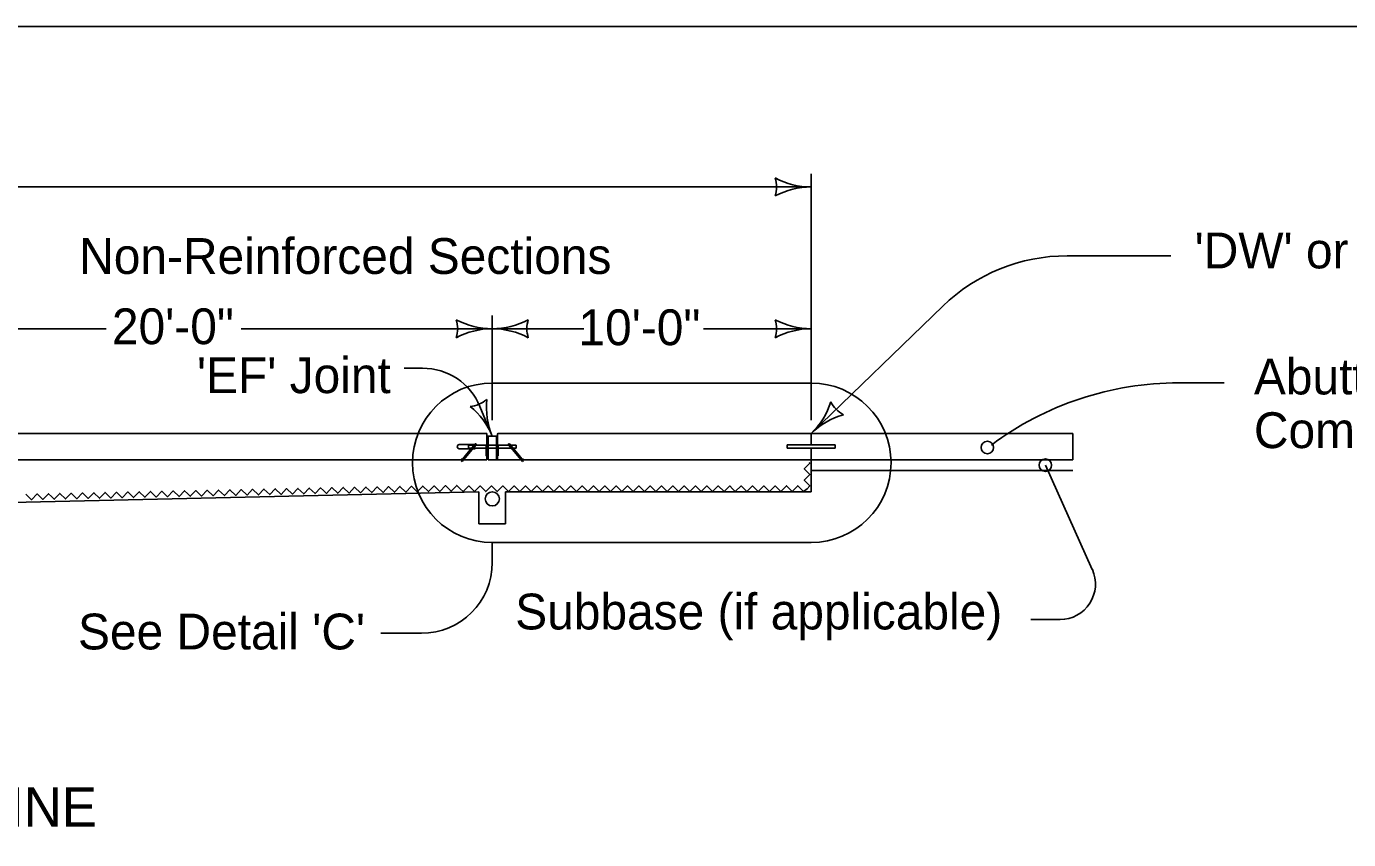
# Model space of a CAD drawing. Extents: x -2135039 to -2120895, y -2139150 to -2136566.
# Drawn here: x -2126431 to -2125693, y -2137490 to -2137036 of the extents above; entities that cross this region are included whole.
import ezdxf

# ---------------------------------------------------------------- set-up
doc = ezdxf.new("R2010")
doc.units = 0
for name, color, linetype in [('dsnStdDimension', 7, 'Continuous'), ('dsnStdLabel', 7, 'Continuous'), ('dsnStdLineWork', 7, 'Continuous'), ('Level 1', 7, 'Continuous'), ('Level 2', 7, 'Continuous'), ('Level 3', 7, 'Continuous')]:
    doc.layers.add(name, color=color, linetype=linetype)

msp = doc.modelspace()

# ---------------------------------------------------------------- linework, layer by layer
at = {"layer": 'dsnStdDimension'}
for p, q in [((-2125992.85, -2137255.84), (-2125992.85, -2137118.21)), ((-2127329.35, -2137125.64), (-2125992.85, -2137125.64)), ((-2126171.05, -2137255.84), (-2126171.05, -2137197.41)), ((-2126527.45, -2137204.84), (-2126386.67, -2137204.84)), ((-2126311.39, -2137204.84), (-2126171.05, -2137204.84)), ((-2126171.05, -2137204.84), (-2126119.93, -2137204.84)), ((-2126052.97, -2137204.84), (-2125992.85, -2137204.84))]:
    msp.add_line(p, q, dxfattribs=at)
for centre, radius, start, end in [((-2126028.7, -2137125.64), 16.51, 342.26665, 17.73335), ((-2125992.85, -2137082.89), 42.75, 241.92751, 270), ((-2126028.7, -2137125.64), 16.51, 342.26665, 17.73335), ((-2125992.85, -2137082.89), 42.75, 241.92751, 270), ((-2125992.85, -2137168.39), 42.75, 90, 118.07249), ((-2125992.85, -2137168.39), 42.75, 90, 118.07249), ((-2126206.9, -2137204.84), 16.51, 342.26665, 17.73335), ((-2126171.05, -2137162.09), 42.75, 241.92751, 270), ((-2126206.9, -2137204.84), 16.51, 342.26665, 17.73335), ((-2126171.05, -2137162.09), 42.75, 241.92751, 270), ((-2126171.05, -2137162.09), 42.75, 270, 298.07249), ((-2126171.05, -2137162.09), 42.75, 270, 298.07249), ((-2126135.21, -2137204.84), 16.51, 162.26665, 197.73335), ((-2126135.21, -2137204.84), 16.51, 162.26665, 197.73335), ((-2126028.7, -2137204.84), 16.51, 342.26665, 17.73335), ((-2125992.85, -2137162.09), 42.75, 241.92751, 270), ((-2126028.7, -2137204.84), 16.51, 342.26665, 17.73335), ((-2125992.85, -2137162.09), 42.75, 241.92751, 270), ((-2126171.05, -2137247.58), 42.75, 90, 118.07249), ((-2126171.05, -2137247.58), 42.75, 90, 118.07249), ((-2126171.05, -2137247.58), 42.75, 61.92751, 90), ((-2126171.05, -2137247.58), 42.75, 61.92751, 90), ((-2125992.85, -2137247.58), 42.75, 90, 118.07249), ((-2125992.85, -2137247.58), 42.75, 90, 118.07249)]:
    msp.add_arc(centre, radius, start, end, dxfattribs=at)
at = {"layer": 'dsnStdLabel'}
for p, q in [((-2125849.87, -2137164.08), (-2125791.98, -2137164.08)), ((-2125992.85, -2137263.26), (-2125919.4, -2137192.21)), ((-2126220.32, -2137226.87), (-2126209.98, -2137226.87)), ((-2126171.05, -2137235.17), (-2125992.85, -2137235.17)), ((-2125787.52, -2137235.01), (-2125762.18, -2137235.01)), ((-2126177.99, -2137248.21), (-2126171.05, -2137264.87)), ((-2125835.83, -2137339.33), (-2125862.07, -2137281.03)), ((-2126171.05, -2137324.27), (-2126171.05, -2137335.37)), ((-2126171.05, -2137324.27), (-2125992.85, -2137324.27)), ((-2125870.11, -2137367.25), (-2125853.87, -2137367.25)), ((-2126233.3, -2137374.97), (-2126210.65, -2137374.97))]:
    msp.add_line(p, q, dxfattribs=at)
for centre in [(-2125894.47, -2137271.16), (-2125862.07, -2137281.03)]:
    msp.add_circle(centre, 3.46, dxfattribs=at)
for centre, radius, start, end in [((-2125849.87, -2137264.08), 100, 90, 134.0496), ((-2126209.98, -2137261.52), 34.65, 22.59071, 90), ((-2126171.05, -2137279.72), 44.55, 90, 270), ((-2125992.85, -2137279.72), 44.55, 270, 90), ((-2125787.52, -2137410.01), 175, 90, 126.74873), ((-2126184.82, -2137231.78), 16.51, 274.85846, 310.32516), ((-2126131.59, -2137248.45), 42.75, 174.51932, 202.59181), ((-2126210.52, -2137281.29), 42.75, 22.59181, 50.6643), ((-2126022.58, -2137232.54), 42.75, 314.04979, 342.12228), ((-2126022.58, -2137232.54), 42.75, 314.04979, 342.12228), ((-2125967.09, -2137238.34), 16.51, 206.31644, 241.78314), ((-2125967.09, -2137238.34), 16.51, 206.31644, 241.78314), ((-2125963.13, -2137293.99), 42.75, 105.97731, 134.04979), ((-2125963.13, -2137293.99), 42.75, 105.97731, 134.04979), ((-2126210.65, -2137335.37), 39.6, 270, 360), ((-2125853.87, -2137347.45), 19.8, 270, 24.23803)]:
    msp.add_arc(centre, radius, start, end, dxfattribs=at)
at = {"layer": 'dsnStdLineWork'}
for p, q in [((-2126174.02, -2137264.87), (-2126173.43, -2137264.87)), ((-2126168.68, -2137264.87), (-2126168.08, -2137264.87)), ((-2125996.2, -2137278.11), (-2125998.11, -2137278.11))]:
    msp.add_line(p, q, dxfattribs=at)
for points in [[(-2125995.17, -2137294.22), (-2125993.58, -2137292.64), (-2125996.75, -2137289.47), (-2125993.59, -2137286.3), (-2125996.76, -2137283.14), (-2125993.59, -2137279.97), (-2125994.02, -2137279.53)], [(-2126431.66, -2137297.24), (-2126428.42, -2137300.34), (-2126425.33, -2137297.1), (-2126422.09, -2137300.2), (-2126418.99, -2137296.97), (-2126417.37, -2137298.52)], [(-2126417.37, -2137298.52), (-2126415.75, -2137300.07), (-2126412.65, -2137296.83), (-2126409.42, -2137299.93), (-2126406.32, -2137296.69), (-2126403.09, -2137299.8), (-2126399.99, -2137296.56), (-2126396.75, -2137299.66), (-2126393.65, -2137296.43), (-2126390.41, -2137299.53), (-2126387.32, -2137296.29), (-2126384.08, -2137299.39), (-2126380.98, -2137296.16), (-2126377.75, -2137299.25), (-2126374.64, -2137296.02), (-2126371.41, -2137299.12), (-2126368.31, -2137295.88), (-2126365.08, -2137298.98), (-2126361.98, -2137295.75), (-2126358.74, -2137298.85), (-2126355.65, -2137295.61), (-2126352.41, -2137298.71), (-2126349.31, -2137295.47), (-2126346.07, -2137298.58), (-2126342.97, -2137295.34), (-2126341.36, -2137296.89)], [(-2126341.36, -2137296.89), (-2126339.74, -2137298.44), (-2126336.64, -2137295.21), (-2126333.41, -2137298.31), (-2126330.3, -2137295.07), (-2126327.07, -2137298.17), (-2126323.97, -2137294.94), (-2126320.73, -2137298.03), (-2126317.64, -2137294.8), (-2126314.4, -2137297.9), (-2126311.3, -2137294.66), (-2126308.07, -2137297.76), (-2126304.97, -2137294.53), (-2126301.73, -2137297.63), (-2126298.63, -2137294.39), (-2126295.4, -2137297.49), (-2126292.3, -2137294.26), (-2126289.06, -2137297.36), (-2126285.96, -2137294.12), (-2126282.73, -2137297.22), (-2126279.63, -2137293.99), (-2126276.39, -2137297.09), (-2126273.29, -2137293.85), (-2126270.06, -2137296.95), (-2126266.96, -2137293.72), (-2126265.34, -2137295.27)], [(-2126265.34, -2137295.27), (-2126263.73, -2137296.82), (-2126260.62, -2137293.6), (-2126257.39, -2137296.71), (-2126254.28, -2137293.49), (-2126251.06, -2137296.6), (-2126247.95, -2137293.38), (-2126244.72, -2137296.49), (-2126241.61, -2137293.27), (-2126238.39, -2137296.38), (-2126235.28, -2137293.16), (-2126232.05, -2137296.27), (-2126228.94, -2137293.05), (-2126225.72, -2137296.16), (-2126222.61, -2137292.94), (-2126219.38, -2137296.05), (-2126216.27, -2137292.83), (-2126213.05, -2137295.94), (-2126209.94, -2137292.72), (-2126206.71, -2137295.83), (-2126203.6, -2137292.61), (-2126200.38, -2137295.72), (-2126197.27, -2137292.49), (-2126194.04, -2137295.61), (-2126190.93, -2137292.38), (-2126188.99, -2137294.26)], [(-2126188.91, -2137294.24), (-2126187.33, -2137295.82), (-2126184.16, -2137292.66), (-2126180.99, -2137295.82), (-2126177.83, -2137292.66), (-2126174.66, -2137295.82), (-2126171.49, -2137292.65), (-2126168.32, -2137295.82), (-2126165.15, -2137292.65), (-2126161.99, -2137295.82), (-2126158.82, -2137292.65), (-2126155.65, -2137295.82), (-2126152.48, -2137292.64), (-2126149.31, -2137295.81), (-2126146.15, -2137292.64), (-2126142.98, -2137295.81), (-2126139.81, -2137292.64), (-2126136.64, -2137295.81), (-2126133.47, -2137292.64), (-2126130.31, -2137295.8), (-2126127.14, -2137292.63), (-2126123.97, -2137295.8), (-2126120.8, -2137292.63), (-2126117.63, -2137295.8), (-2126114.47, -2137292.63), (-2126112.88, -2137294.21)], [(-2126112.88, -2137294.21), (-2126111.3, -2137295.8), (-2126108.13, -2137292.62), (-2126104.96, -2137295.79), (-2126101.79, -2137292.62), (-2126098.63, -2137295.79), (-2126095.46, -2137292.62), (-2126092.29, -2137295.79), (-2126089.12, -2137292.62), (-2126085.95, -2137295.78), (-2126082.79, -2137292.62), (-2126079.62, -2137295.78), (-2126076.45, -2137292.62), (-2126073.28, -2137295.78), (-2126070.11, -2137292.61), (-2126066.95, -2137295.78), (-2126063.78, -2137292.61), (-2126060.61, -2137295.78), (-2126057.44, -2137292.61), (-2126054.27, -2137295.78), (-2126051.11, -2137292.6), (-2126047.94, -2137295.77), (-2126044.77, -2137292.6), (-2126041.6, -2137295.77), (-2126038.43, -2137292.6), (-2126036.85, -2137294.18)], [(-2126036.85, -2137294.18), (-2126035.27, -2137295.77), (-2126032.1, -2137292.6), (-2126028.93, -2137295.76), (-2126025.76, -2137292.59), (-2126022.59, -2137295.76), (-2126019.43, -2137292.59), (-2126016.26, -2137295.76), (-2126013.09, -2137292.59), (-2126009.92, -2137295.76), (-2126006.75, -2137292.58), (-2126003.59, -2137295.75), (-2126000.42, -2137292.58), (-2125997.25, -2137295.75), (-2125995.17, -2137294.22)]]:
    msp.add_lwpolyline(points, dxfattribs=at)
at = {"layer": 'Level 1'}
msp.add_lwpolyline([(-2127734.46, -2137035.95), (-2124599.46, -2137035.95), (-2124599.46, -2139045.94), (-2127734.46, -2139045.94)], close=True, dxfattribs=at)
at = {"layer": 'Level 2'}
for p, q in [((-2127329.35, -2137263.26), (-2126174.44, -2137263.26)), ((-2126174.44, -2137263.26), (-2126527.46, -2137263.26)), ((-2126174.03, -2137269.78), (-2126174.03, -2137263.68)), ((-2126174.02, -2137273.6), (-2126174.02, -2137263.68)), ((-2126173.97, -2137264.87), (-2126173.97, -2137273.6)), ((-2126173.91, -2137264.87), (-2126173.91, -2137273.6)), ((-2126173.85, -2137264.87), (-2126173.85, -2137273.6)), ((-2126173.79, -2137264.87), (-2126173.79, -2137273.6)), ((-2126173.73, -2137264.87), (-2126173.73, -2137273.6)), ((-2126173.67, -2137264.87), (-2126173.67, -2137273.6)), ((-2126173.61, -2137264.87), (-2126173.61, -2137273.6)), ((-2126173.55, -2137264.87), (-2126173.55, -2137273.6)), ((-2126173.49, -2137264.87), (-2126173.49, -2137273.6)), ((-2126173.43, -2137264.87), (-2126173.43, -2137269.8)), ((-2126168.68, -2137264.87), (-2126173.43, -2137264.87)), ((-2126173.43, -2137264.87), (-2126173.43, -2137269.8)), ((-2126168.68, -2137269.8), (-2126168.68, -2137264.87)), ((-2126168.62, -2137264.87), (-2126168.62, -2137273.6)), ((-2126168.56, -2137264.87), (-2126168.56, -2137273.6)), ((-2126168.5, -2137264.87), (-2126168.5, -2137273.6)), ((-2126168.44, -2137264.87), (-2126168.44, -2137273.6)), ((-2126168.39, -2137264.87), (-2126168.39, -2137273.6)), ((-2126168.32, -2137264.87), (-2126168.32, -2137273.6)), ((-2126168.27, -2137264.87), (-2126168.27, -2137273.6)), ((-2126168.2, -2137264.87), (-2126168.2, -2137273.6)), ((-2126168.15, -2137264.87), (-2126168.15, -2137273.6)), ((-2126168.09, -2137263.68), (-2126168.09, -2137269.8)), ((-2126168.08, -2137273.6), (-2126168.08, -2137263.68)), ((-2126167.67, -2137263.26), (-2125992.85, -2137263.26)), ((-2125992.86, -2137263.27), (-2126167.67, -2137263.26)), ((-2125992.86, -2137269.76), (-2125992.86, -2137263.27)), ((-2125992.85, -2137263.26), (-2125992.85, -2137269.76)), ((-2125992.85, -2137263.26), (-2125846.67, -2137263.26)), ((-2125846.67, -2137263.26), (-2125846.67, -2137278.11)), ((-2126189.47, -2137269.5), (-2126180.91, -2137269.5)), ((-2126189.47, -2137271.88), (-2126182.9, -2137271.88)), ((-2126184.34, -2137273.6), (-2126186.09, -2137275.69)), ((-2126183.41, -2137273.6), (-2126185.17, -2137275.69)), ((-2126184.42, -2137271.58), (-2126184.42, -2137269.8)), ((-2126184.42, -2137269.8), (-2126181.15, -2137269.8)), ((-2126184.42, -2137271.58), (-2126182.65, -2137271.58)), ((-2126180.66, -2137269.21), (-2126184.34, -2137273.6)), ((-2126183.41, -2137273.6), (-2126180.12, -2137269.67)), ((-2126181.97, -2137271.88), (-2126180.56, -2137271.88)), ((-2126181.72, -2137271.58), (-2126174.38, -2137271.58)), ((-2126180.56, -2137271.58), (-2126180.56, -2137271.88)), ((-2126180.23, -2137269.8), (-2126174.38, -2137269.8)), ((-2126174.39, -2137275.74), (-2126174.39, -2137269.8)), ((-2126174.38, -2137275.74), (-2126174.38, -2137269.8)), ((-2126174.02, -2137275.69), (-2126174.02, -2137273.6)), ((-2126173.97, -2137273.6), (-2126173.97, -2137275.69)), ((-2126173.91, -2137273.6), (-2126173.91, -2137275.69)), ((-2126173.85, -2137273.6), (-2126173.85, -2137275.69)), ((-2126173.79, -2137273.6), (-2126173.79, -2137275.69)), ((-2126173.73, -2137273.6), (-2126173.73, -2137275.69)), ((-2126173.67, -2137273.6), (-2126173.67, -2137275.69)), ((-2126173.61, -2137273.6), (-2126173.61, -2137275.69)), ((-2126173.55, -2137273.6), (-2126173.55, -2137275.69)), ((-2126173.49, -2137273.6), (-2126173.49, -2137275.69)), ((-2126173.43, -2137269.8), (-2126173.43, -2137271.58)), ((-2126173.43, -2137269.8), (-2126168.68, -2137269.8)), ((-2126173.43, -2137271.58), (-2126168.68, -2137271.58)), ((-2126173.43, -2137271.58), (-2126173.43, -2137273.6)), ((-2126173.43, -2137273.6), (-2126173.43, -2137275.69)), ((-2126168.68, -2137269.8), (-2126168.68, -2137271.58)), ((-2126168.68, -2137271.58), (-2126168.68, -2137273.6)), ((-2126168.68, -2137273.6), (-2126168.68, -2137275.69)), ((-2126168.62, -2137273.6), (-2126168.62, -2137275.69)), ((-2126168.56, -2137273.6), (-2126168.56, -2137275.69)), ((-2126168.5, -2137273.6), (-2126168.5, -2137275.69)), ((-2126168.44, -2137273.6), (-2126168.44, -2137275.69)), ((-2126168.39, -2137273.6), (-2126168.39, -2137275.69)), ((-2126168.32, -2137273.6), (-2126168.32, -2137275.69)), ((-2126168.27, -2137273.6), (-2126168.27, -2137275.69)), ((-2126168.2, -2137273.6), (-2126168.2, -2137275.69)), ((-2126168.15, -2137273.6), (-2126168.15, -2137275.69)), ((-2126168.08, -2137275.69), (-2126168.08, -2137273.6)), ((-2126167.73, -2137269.8), (-2126167.73, -2137275.74)), ((-2126167.73, -2137275.74), (-2126167.73, -2137269.8)), ((-2126167.73, -2137269.8), (-2126161.89, -2137269.8)), ((-2126167.73, -2137271.58), (-2126160.39, -2137271.58)), ((-2126158.7, -2137273.6), (-2126161.99, -2137269.67)), ((-2126161.45, -2137269.21), (-2126157.77, -2137273.6)), ((-2126160.96, -2137269.8), (-2126157.69, -2137269.8)), ((-2126159.46, -2137271.58), (-2126157.69, -2137271.58)), ((-2126158.7, -2137273.6), (-2126156.94, -2137275.69)), ((-2126157.77, -2137273.6), (-2126156.01, -2137275.69)), ((-2126157.69, -2137271.58), (-2126157.69, -2137269.8)), ((-2126006.23, -2137271.62), (-2126006.23, -2137269.76)), ((-2126006.23, -2137269.76), (-2125992.86, -2137269.76)), ((-2125992.86, -2137271.62), (-2126006.23, -2137271.62)), ((-2126006.22, -2137271.62), (-2126006.22, -2137269.76)), ((-2126006.22, -2137269.76), (-2125979.49, -2137269.76)), ((-2125979.49, -2137271.62), (-2126006.22, -2137271.62)), ((-2125992.86, -2137278.11), (-2125992.86, -2137271.62)), ((-2125992.85, -2137271.62), (-2125992.85, -2137278.11)), ((-2125979.49, -2137269.76), (-2125979.49, -2137271.62)), ((-2126188.13, -2137278.11), (-2127329.35, -2137278.11)), ((-2126527.46, -2137278.11), (-2126188.14, -2137278.11)), ((-2126186.09, -2137275.69), (-2126188.51, -2137278.57)), ((-2126187.96, -2137279.03), (-2126188.51, -2137278.57)), ((-2126188.14, -2137278.11), (-2126174.03, -2137278.11)), ((-2126185.17, -2137275.69), (-2126187.96, -2137279.03)), ((-2126174.02, -2137278.11), (-2126187.2, -2137278.11)), ((-2126174.03, -2137278.11), (-2126174.03, -2137275.74)), ((-2126174.02, -2137278.11), (-2126174.02, -2137275.69)), ((-2126173.97, -2137275.69), (-2126173.97, -2137278.11)), ((-2126173.91, -2137275.69), (-2126173.91, -2137278.11)), ((-2126173.85, -2137275.69), (-2126173.85, -2137278.11)), ((-2126173.79, -2137275.69), (-2126173.79, -2137278.11)), ((-2126173.73, -2137275.69), (-2126173.73, -2137278.11)), ((-2126173.67, -2137275.69), (-2126173.67, -2137278.11)), ((-2126173.61, -2137275.69), (-2126173.61, -2137278.11)), ((-2126173.55, -2137275.69), (-2126173.55, -2137278.11)), ((-2126173.49, -2137275.69), (-2126173.49, -2137278.11)), ((-2126173.43, -2137275.69), (-2126173.43, -2137278.11)), ((-2126173.43, -2137278.11), (-2126168.68, -2137278.11)), ((-2126168.68, -2137275.69), (-2126168.68, -2137278.11)), ((-2126168.68, -2137278.11), (-2125992.85, -2137278.11)), ((-2126168.62, -2137275.69), (-2126168.62, -2137278.11)), ((-2126168.56, -2137275.69), (-2126168.56, -2137278.11)), ((-2126168.5, -2137275.69), (-2126168.5, -2137278.11)), ((-2126168.44, -2137275.69), (-2126168.44, -2137278.11)), ((-2126168.39, -2137275.69), (-2126168.39, -2137278.11)), ((-2126168.32, -2137275.69), (-2126168.32, -2137278.11)), ((-2126168.27, -2137275.69), (-2126168.27, -2137278.11)), ((-2126168.2, -2137275.69), (-2126168.2, -2137278.11)), ((-2126168.15, -2137275.69), (-2126168.15, -2137278.11)), ((-2126168.09, -2137275.74), (-2126168.09, -2137278.11)), ((-2126168.09, -2137278.11), (-2125992.86, -2137278.11)), ((-2126168.08, -2137278.11), (-2126168.08, -2137275.69)), ((-2126156.94, -2137275.69), (-2126154.15, -2137279.03)), ((-2126156.01, -2137275.69), (-2126153.6, -2137278.57)), ((-2126154.15, -2137279.03), (-2126153.6, -2137278.57)), ((-2125992.85, -2137278.11), (-2125992.85, -2137295.93)), ((-2125992.85, -2137278.11), (-2125846.67, -2137278.11)), ((-2125846.67, -2137284.05), (-2125992.85, -2137284.05)), ((-2126178.48, -2137295.93), (-2127295.72, -2137321.18)), ((-2126178.48, -2137295.93), (-2126178.48, -2137313.75)), ((-2126163.63, -2137295.93), (-2125992.85, -2137295.93)), ((-2126163.63, -2137295.93), (-2126163.63, -2137313.75)), ((-2126178.48, -2137313.75), (-2126163.63, -2137313.75))]:
    msp.add_line(p, q, dxfattribs=at)
msp.add_lwpolyline([(-2126168.09, -2137269.8), (-2126168.09, -2137269.8)], dxfattribs=at)
for centre, radius in [((-2126183.41, -2137272.12), 0.238), ((-2126158.95, -2137271.82), 0.238), ((-2126188.24, -2137277.88), 0.238), ((-2126153.87, -2137277.88), 0.238), ((-2126171.05, -2137299.89), 3.96)]:
    msp.add_circle(centre, radius, dxfattribs=at)
for centre, radius, start, end in [((-2126174.44, -2137263.68), 0.416, 360, 90), ((-2126174.44, -2137263.68), 0.416, 0, 90), ((-2126167.67, -2137263.68), 0.416, 90, 180), ((-2126167.67, -2137263.68), 0.416, 90, 180), ((-2126189.47, -2137270.69), 1.19, 90, 270), ((-2126180.39, -2137269.44), 0.356, 320.00367, 139.99636), ((-2126174.21, -2137269.8), 0.178, 5.43269, 180), ((-2126174.2, -2137269.8), 0.178, 0, 180), ((-2126167.91, -2137269.8), 0.178, 0, 180), ((-2126167.91, -2137269.8), 0.178, 0, 180), ((-2126161.72, -2137269.44), 0.356, 40.00364, 219.99633), ((-2126174.21, -2137275.74), 0.178, 180, 359.93724), ((-2126174.2, -2137275.74), 0.178, 180, 0), ((-2126167.91, -2137275.74), 0.178, 180, 0), ((-2126167.91, -2137275.74), 0.178, 180, 0)]:
    msp.add_arc(centre, radius, start, end, dxfattribs=at)
for points in [[(-2126167.73, -2137269.92), (-2126167.7, -2137269.92), (-2126167.67, -2137269.92), (-2126167.64, -2137269.92), (-2126167.62, -2137269.92), (-2126167.6, -2137269.92), (-2126167.59, -2137269.92)], [(-2126167.73, -2137270.04), (-2126167.7, -2137270.04), (-2126167.67, -2137270.04), (-2126167.64, -2137270.04), (-2126167.62, -2137270.04), (-2126167.6, -2137270.04), (-2126167.59, -2137270.04)], [(-2126167.73, -2137270.16), (-2126167.7, -2137270.16), (-2126167.67, -2137270.16), (-2126167.64, -2137270.16), (-2126167.62, -2137270.16), (-2126167.6, -2137270.16), (-2126167.59, -2137270.16)], [(-2126167.73, -2137270.27), (-2126167.7, -2137270.28), (-2126167.67, -2137270.27), (-2126167.64, -2137270.27), (-2126167.62, -2137270.27), (-2126167.6, -2137270.28), (-2126167.59, -2137270.27)], [(-2126167.73, -2137270.39), (-2126167.7, -2137270.4), (-2126167.67, -2137270.39), (-2126167.64, -2137270.39), (-2126167.62, -2137270.39), (-2126167.6, -2137270.4), (-2126167.59, -2137270.39)], [(-2126167.73, -2137270.51), (-2126167.7, -2137270.52), (-2126167.67, -2137270.51), (-2126167.64, -2137270.51), (-2126167.62, -2137270.51), (-2126167.6, -2137270.52), (-2126167.59, -2137270.51)], [(-2126167.73, -2137270.63), (-2126167.7, -2137270.63), (-2126167.67, -2137270.63), (-2126167.64, -2137270.63), (-2126167.62, -2137270.63), (-2126167.6, -2137270.63), (-2126167.59, -2137270.63)], [(-2126167.73, -2137270.75), (-2126167.7, -2137270.75), (-2126167.67, -2137270.75), (-2126167.64, -2137270.75), (-2126167.62, -2137270.75), (-2126167.6, -2137270.75), (-2126167.59, -2137270.75)], [(-2126167.73, -2137270.87), (-2126167.7, -2137270.87), (-2126167.67, -2137270.87), (-2126167.64, -2137270.87), (-2126167.62, -2137270.87), (-2126167.6, -2137270.87), (-2126167.59, -2137270.87)], [(-2126167.73, -2137270.99), (-2126167.7, -2137270.99), (-2126167.67, -2137270.99), (-2126167.64, -2137270.99), (-2126167.62, -2137270.99), (-2126167.6, -2137270.99), (-2126167.59, -2137270.99)], [(-2126167.73, -2137271.11), (-2126167.7, -2137271.11), (-2126167.67, -2137271.11), (-2126167.64, -2137271.11), (-2126167.62, -2137271.11), (-2126167.6, -2137271.11), (-2126167.59, -2137271.11)], [(-2126167.73, -2137271.22), (-2126167.7, -2137271.23), (-2126167.67, -2137271.22), (-2126167.64, -2137271.22), (-2126167.62, -2137271.22), (-2126167.6, -2137271.23), (-2126167.59, -2137271.22)], [(-2126167.73, -2137271.34), (-2126167.7, -2137271.35), (-2126167.67, -2137271.34), (-2126167.64, -2137271.34), (-2126167.62, -2137271.34), (-2126167.6, -2137271.35), (-2126167.59, -2137271.34)], [(-2126167.73, -2137271.46), (-2126167.7, -2137271.47), (-2126167.67, -2137271.46), (-2126167.64, -2137271.46), (-2126167.62, -2137271.46), (-2126167.6, -2137271.47), (-2126167.59, -2137271.46)]]:
    msp.add_spline(points, degree=3, dxfattribs=at)

# ---------------------------------------------------------------- texts
at = {"layer": 'dsnStdDimension'}
for s, p in [('Non-Reinforced Sections', (-2126401.82, -2137174.19)), ('20\'-0"', (-2126383.54, -2137213.47)), ('10\'-0"', (-2126122.91, -2137214.02))]:
    msp.add_text(s, height=20, dxfattribs=at).set_placement(p)
at = {"layer": 'dsnStdLabel'}
for s, p in [("'DW' or 'RT' Joint", (-2125778.68, -2137171.11)), ("'EF' Joint", (-2126336.05, -2137240.8)), ('Abutting PCC or', (-2125745.55, -2137241.51)), ('Composite Pavement', (-2125745.55, -2137271.51)), ('Subbase (if applicable)', (-2126158.23, -2137372.81)), ("See Detail 'C'", (-2126402.48, -2137383.98))]:
    msp.add_text(s, height=20, dxfattribs=at).set_placement(p)
at = {"layer": 'Level 3'}
msp.add_text('SECTION THRU CENTERLINE', height=22, dxfattribs=at).set_placement((-2126807.08, -2137483.03))

doc.saveas('drawing.dxf')
